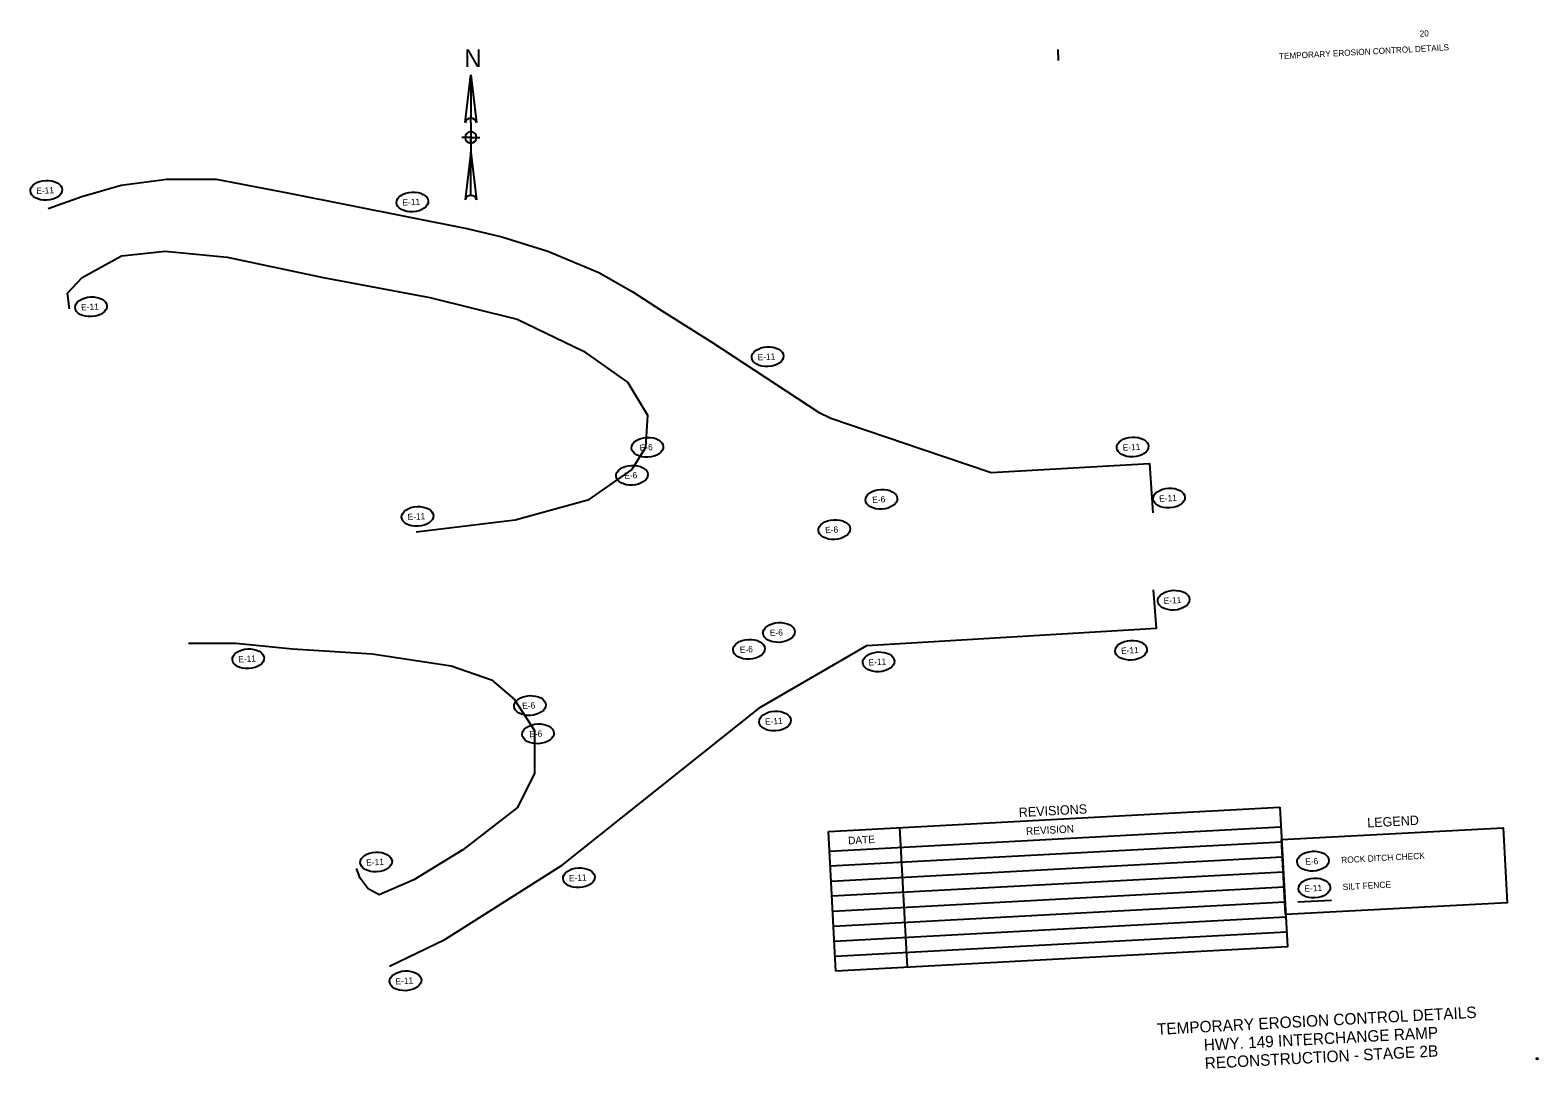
# Model space of a CAD drawing. Extents: x 251493 to 254667, y 216764 to 225410.
# Drawn here: x 251778 to 254667, y 216764 to 218754 of the extents above; entities that cross this region are included whole.
import ezdxf

# ---------------------------------------------------------------- set-up
doc = ezdxf.new("R2010")
doc.units = 0
for name, color, linetype in [('24X36', 7, 'Continuous'), ('Level 1', 7, 'Continuous'), ('Level 2', 7, 'Continuous'), ('Level 30', 7, 'Continuous'), ('R_Border', 7, 'Continuous')]:
    doc.layers.add(name, color=color, linetype=linetype)

msp = doc.modelspace()

# ---------------------------------------------------------------- linework, layer by layer
at = {"layer": '24X36'}
msp.add_line((254207.3, 217083.5), (254271.3, 217086.9), dxfattribs=at)
for points in [[(251813, 218412.6), (251877, 218435.7), (251952.4, 218457.4), (252040, 218469), (252134.5, 218468.6), (252274.3, 218442), (252614.7, 218374.2), (252682.2, 218358.1), (252769.8, 218331), (252868, 218289.7), (252931.5, 218253.3), (252987.9, 218217.1), (253084.1, 218156.5), (253288.9, 218022.2), (253312.3, 218010.9), (253487.1, 217951.5), (253619.3, 217906.5), (253923, 217923.7), (253929.3, 217828.9)], [(251853.5, 218220.4), (251849.6, 218250.1), (251877.8, 218280.3), (251953.4, 218321.5), (252036.6, 218330.7), (252155.6, 218319.1), (252339.5, 218280), (252543.7, 218241.9), (252711, 218200.6), (252838.6, 218139.3), (252923.2, 218079.2), (252961.2, 218016.7), (252957.4, 217954.3), (252930.9, 217912.2), (252846.8, 217853.8), (252707.7, 217815.3), (252517.6, 217791.9)], [(252466.9, 216960.3), (252573, 217011.4), (252797.4, 217153.8), (253177.8, 217456.5), (253381.4, 217574.7), (253936.1, 217608), (253930.3, 217681.9)], [(252081.6, 217579.6), (252172.5, 217579.7), (252280.7, 217568.8), (252433.2, 217559), (252585.1, 217536), (252661.9, 217509), (252705.7, 217471.9), (252744.8, 217411.8), (252744.4, 217330.5), (252712.1, 217264.2), (252607, 217183.2), (252513.2, 217126.1), (252447.2, 217096.9), (252425.6, 217108.3), (252410.2, 217129), (252403.2, 217147.7)]]:
    msp.add_lwpolyline(points, dxfattribs=at)
for centre in [(251809.1, 218447.3), (252510.6, 218425.1), (251894.9, 218224.1), (253191.2, 218128.4), (252960.9, 217954.8), (253890.5, 217955.4), (252931.2, 217901.2), (253409.1, 217855.2), (253960.4, 217857.5), (252520.4, 217822.3), (253318.9, 217797.1), (253969.1, 217661.8), (253212.9, 217599.9), (253155.4, 217567.7), (253887.5, 217565.9), (252196, 217549.5), (253403.7, 217543.6), (252735.7, 217459.9), (253205.3, 217430.1), (252751.4, 217405.7), (252441.1, 217160), (252829.6, 217129.8), (252497.3, 216932.3)]:
    msp.add_ellipse(centre, major_axis=(30.4, 1.6), ratio=0.622507, dxfattribs=at)
at = {"layer": 'Level 1'}
for p, q in [((252611.6, 218577), (252622.5, 218668.4)), ((252622.5, 218668.4), (252633.4, 218577)), ((252622.5, 218668.4), (252622.5, 218585.7)), ((252622.5, 218577), (252622.5, 218585.7)), ((252622.5, 218577), (252622.5, 218559.5)), ((252611.2, 218548.7), (252605.1, 218548.7)), ((252622.5, 218548.7), (252612, 218548.7)), ((252622.5, 218559.5), (252622.5, 218548.7)), ((252622.5, 218548.7), (252622.5, 218537.8)), ((252622.5, 218548.7), (252633.4, 218548.7)), ((252622.5, 218537.8), (252622.5, 218548.7)), ((252622.5, 218537.8), (252622.5, 218520.4)), ((252633.4, 218548.7), (252639.9, 218548.7)), ((252633.4, 218548.7), (252633.4, 218548.7)), ((252622.5, 218520.4), (252611.6, 218428.9)), ((252622.5, 218437.6), (252622.5, 218520.4)), ((252622.5, 218520.4), (252633.4, 218428.9)), ((253307.7, 217218.6), (254172.7, 217264.9)), ((254172.7, 217264.9), (254187, 216997.4)), ((253322, 216951.1), (253307.7, 217218.6)), ((253309.7, 217181.1), (254174.7, 217227.5)), ((253444, 217225.9), (253458.4, 216958.4)), ((253311.2, 217152.4), (254176.2, 217198.7)), ((253312.7, 217123.6), (254177.8, 217170)), ((253314.3, 217094.9), (254179.3, 217141.2)), ((253315.8, 217066.1), (254180.8, 217112.4)), ((253317.4, 217037.3), (254182.4, 217083.7)), ((253318.9, 217008.6), (254183.9, 217054.9)), ((253320.5, 216979.8), (254185.5, 217026.2)), ((254187, 216997.4), (253322, 216951.1)), ((254187, 216997.4), (254187, 216997.4))]:
    msp.add_line(p, q, dxfattribs=at)
msp.add_lwpolyline([(254176, 217203.1), (254600.2, 217225.8), (254607.9, 217082), (254183.7, 217059.3)], close=True, dxfattribs=at)
for points in [[(254665, 216783.6), (254663.6, 216783.5), (254663.6, 216783.4), (254664.1, 216783.4), (254664.2, 216781.9), (254664.5, 216781.9), (254664.4, 216783.4), (254665, 216783.5), (254665, 216783.6)], [(254665, 216783.6), (254663.6, 216783.5), (254663.6, 216783.4), (254664.1, 216783.4), (254664.2, 216781.9), (254664.5, 216781.9), (254664.4, 216783.4), (254665, 216783.5), (254665, 216783.6)], [(254665, 216783.6), (254663.6, 216783.5), (254663.6, 216783.4), (254664.1, 216783.4), (254664.2, 216781.9), (254664.5, 216781.9), (254664.4, 216783.4), (254665, 216783.5), (254665, 216783.6)], [(254665.4, 216783.4), (254665.4, 216783.4), (254666, 216782), (254666.2, 216782), (254666.6, 216783.4), (254666.6, 216783.4), (254666.7, 216782), (254666.9, 216782), (254666.8, 216783.7), (254666.5, 216783.7), (254666.1, 216782.3), (254665.4, 216783.6), (254665.1, 216783.6), (254665.2, 216781.9), (254665.5, 216782), (254665.4, 216783.4)], [(254665.4, 216783.4), (254665.4, 216783.4), (254666, 216782), (254666.2, 216782), (254666.6, 216783.4), (254666.6, 216783.4), (254666.7, 216782), (254666.9, 216782), (254666.8, 216783.7), (254666.5, 216783.7), (254666.1, 216782.3), (254665.4, 216783.6), (254665.1, 216783.6), (254665.2, 216781.9), (254665.5, 216782), (254665.4, 216783.4)], [(254665.4, 216783.4), (254665.4, 216783.4), (254666, 216782), (254666.2, 216782), (254666.6, 216783.4), (254666.6, 216783.4), (254666.7, 216782), (254666.9, 216782), (254666.8, 216783.7), (254666.5, 216783.7), (254666.1, 216782.3), (254665.4, 216783.6), (254665.1, 216783.6), (254665.2, 216781.9), (254665.5, 216782), (254665.4, 216783.4)]]:
    msp.add_lwpolyline(points, dxfattribs=at)
for centre, radius, start, end in [((252622.5, 218574.5), 11.2, 90, 167.3196), ((252622.5, 218574.5), 11.2, 12.6804, 90), ((252622.5, 218548.7), 10.9, 90, 180), ((252622.5, 218548.7), 10.9, 180, 270), ((252622.5, 218548.7), 10.9, 0, 90), ((252622.5, 218548.7), 10.9, 270, 0), ((252622.5, 218426.5), 11.2, 90, 167.3196), ((252622.5, 218426.5), 11.2, 12.6804, 90)]:
    msp.add_arc(centre, radius, start, end, dxfattribs=at)
at = {"layer": 'Level 30'}
for centre in [(254236, 217161.6), (254238.8, 217110.1)]:
    msp.add_ellipse(centre, major_axis=(30.4, 1.6), ratio=0.622507, dxfattribs=at)
at = {"layer": 'R_Border'}
msp.add_line((253748.8, 218696.3), (253747.7, 218717), dxfattribs=at)

# ---------------------------------------------------------------- texts
at = {"layer": '24X36'}
for s, p in [('E-11', (251790.3, 218440.1)), ('E-11', (252491.8, 218417.9)), ('E-11', (251876.1, 218217)), ('E-11', (253172.4, 218121.3)), ('E-6', (252946.4, 217947.9)), ('E-11', (253871.8, 217948.2)), ('E-6', (252916.7, 217894.3)), ('E-6', (253391.9, 217848.1)), ('E-11', (253941.6, 217850.3)), ('E-11', (252501.6, 217815.1)), ('E-6', (253301.7, 217790.1)), ('E-11', (253950.3, 217654.6)), ('E-6', (253195.7, 217592.9)), ('E-11', (252177.2, 217542.4)), ('E-6', (253138.2, 217560.6)), ('E-11', (253868.7, 217558.8)), ('E-11', (253384.9, 217536.4)), ('E-6', (252721.2, 217453)), ('E-11', (253186.5, 217423)), ('E-6', (252734.8, 217399)), ('E-11', (252422.3, 217152.9)), ('E-11', (252810.8, 217122.7)), ('E-11', (252478.5, 216925.1))]:
    msp.add_text(s, height=12, rotation=3.0666, dxfattribs=at).set_placement(p)
at = {"layer": 'Level 1'}
for s, height, p in [('20', 11.72, (254440.9, 218741.6)), ('TEMPORARY EROSION CONTROL DETAILS', 11.7, (254171.3, 218698.3)), ('DATE', 14.4, (253345.8, 217193.8)), ('REVISION', 14.4, (253686.6, 217211.8))]:
    msp.add_text(s, height=height, rotation=3.0666, dxfattribs=at).set_placement(p)
msp.add_text('N', height=34.2, dxfattribs=at).set_placement((252609.9, 218683.5))
at = {"layer": 'Level 2'}
for s, p in [('TEMPORARY EROSION CONTROL DETAILS', (253937.8, 216828.6)), ('HWY. 149 INTERCHANGE RAMP', (254027.5, 216798.4)), ('RECONSTRUCTION - STAGE 2B', (254029.3, 216763.4))]:
    msp.add_text(s, height=22, rotation=3.0666, dxfattribs=at).set_placement(p)
at = {"layer": 'Level 30'}
for s, height, p in [('REVISIONS', 18, (253672.8, 217246)), ('LEGEND', 18, (254340.5, 217226.1)), ('ROCK DITCH CHECK', 11.997, (254290.5, 217157.7)), ('E-6', 12, (254221.5, 217154.7)), ('SILT FENCE ', 11.997, (254293.2, 217106.2)), ('E-11', 12, (254220, 217103))]:
    msp.add_text(s, height=height, rotation=3.0666, dxfattribs=at).set_placement(p)

doc.saveas('drawing.dxf')
